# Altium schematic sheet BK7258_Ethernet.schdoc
size 335 x 105 mm
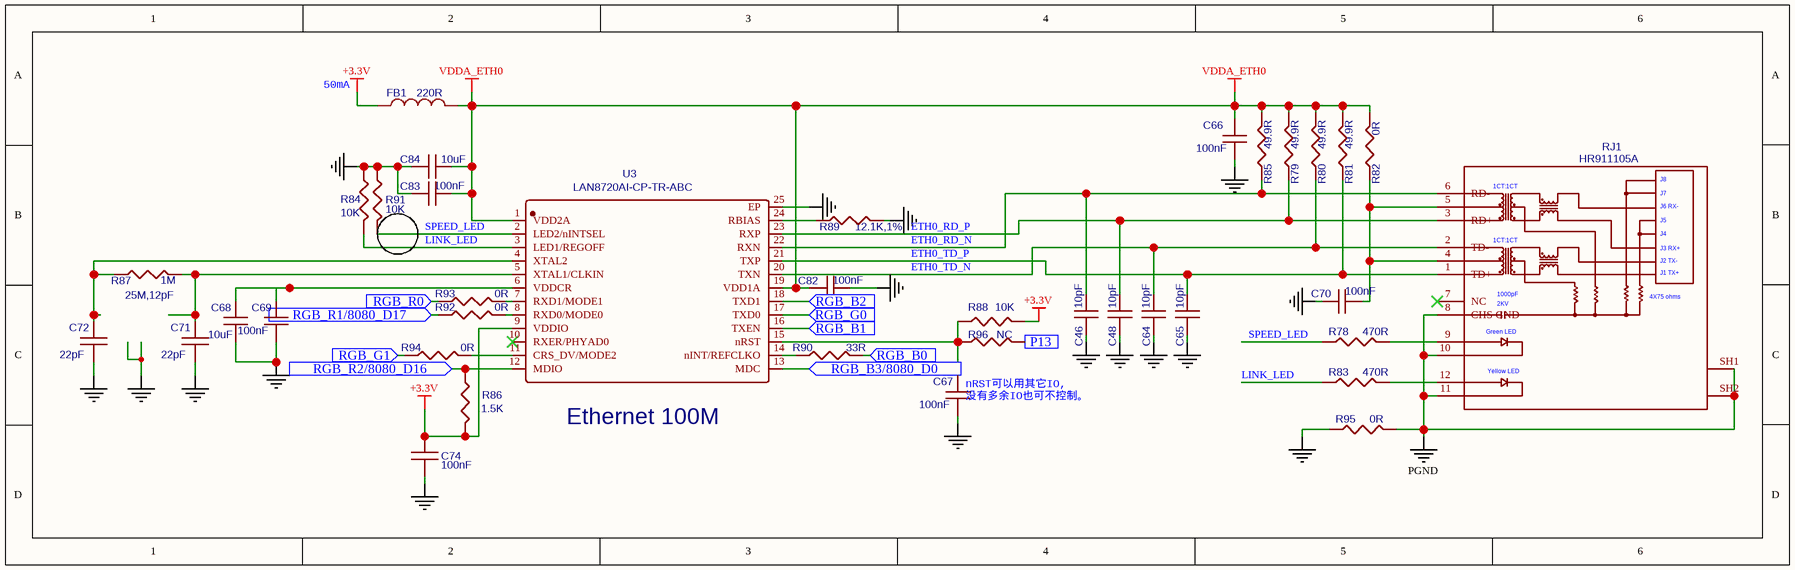
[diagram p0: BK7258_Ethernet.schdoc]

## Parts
C46  10pF  [C0402]
C48  10pF  [C0402]
C64  10pF  [C0402]
C65  10pF  [C0402]
C66  100nF  [C0402]
C67  100nF  [C0402]
C68  10uF  [C0402]
C69  100nF  [C0402]
C70  100nF  [C0402]
C71  22pF  [C0402]
C72  22pF  [C0402]
C74  100nF  [C0402]
C82  100nF  [C0402]
C83  100nF  [C0402]
C84  10uF  [C0402]
FB1  220R  [FB]
R78  470R  [R0402]
R79  49.9R  [R0402]
R80  49.9R  [R0402]
R81  49.9R  [R0402]
R82  0R  [R0402]
R83  470R  [R0402]
R84  10K  [R0402]
R85  49.9R  [R0402]
R86  1.5K  [R0402]
R87  1M  [R0402]
R88  10K  [R0402]
R89  12.1K,1%  [R0402]
R90  33R  [R0402]
R91  10K  [R0402]
R92  0R  [R0402]
R93  0R  [R0402]
R94  0R  [R0402]
R95  0R  [R0402]
R96  NC  [R0402]
RJ1  HR911105A  [RJ45-TH_HR911105A]
U3  LAN8720AI-CP-TR-ABC  [QFN-24_L4.0-W4.0-P0.50-TL-EP2.5]
X3  25M,12pF  [3225_2016]

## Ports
P13 (in), RGB_B0 (in), RGB_B1 (in), RGB_B2 (in), RGB_B3/8080_D0 (in), RGB_G0 (in), RGB_G1 (in), RGB_R0 (in), RGB_R1/8080_D17 (in), RGB_R2/8080_D16 (in)

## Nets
+3.3V: C74.1 FB1.P$1 R86.2 R88.2 U3.9(VDDIO)
GGND: C46.2 C48.2 C64.2 C65.2 C66.2 C67.2 C68.2 C69.2 C70.1 C71.2 C72.2 C74.2 C82.1 C83.2 C84.2 R84.1 R89.2 R91.1 R95.1 U3.25(EP)
PGND: R95.2 RJ1.8(CHS_GND) RJ1.10 RJ1.11 RJ1.SH1 RJ1.SH2
VDDA_ETH0: C66.1 C82.2 C83.1 C84.1 FB1.P$2 R79.2 R80.2 R81.2 R82.2 R85.2 U3.1(VDD2A) U3.19(VDD1A)
ETH0_RD_N: C46.1 R85.1 RJ1.6(RD-) U3.22(RXN)
ETH0_RD_P: C48.1 R79.1 RJ1.3(RD+) U3.23(RXP)
ETH0_TD_N: C64.1 R80.1 RJ1.2(TD-) U3.20(TXN)
ETH0_TD_P: C65.1 R81.1 RJ1.1(TD+) U3.21(TXP)
LINK_LED: R83.1 R84.2 U3.3(LED1/REGOFF)
P13: R96.2 ; port P13
RGB_B0: R90.2 ; port RGB_B0
RGB_B1: U3.16(TXEN) ; port RGB_B1
RGB_B2: U3.18(TXD1) ; port RGB_B2
RGB_B3/8080_D0: U3.13(MDC) ; port RGB_B3/8080_D0
RGB_G0: U3.17(TXD0) ; port RGB_G0
RGB_G1: R94.1 ; port RGB_G1
RGB_R0: R93.1 ; port RGB_R0
RGB_R1/8080_D17: R92.1 ; port RGB_R1/8080_D17
RGB_R2/8080_D16: R86.1 U3.12(MDIO) ; port RGB_R2/8080_D16
SPEED_LED: R78.1 R91.2 U3.2(LED2/nINTSEL)
NetC67_1: C67.1 R88.1 R96.1 U3.15(nRST)
NetC68_1: C68.1 C69.1 U3.6(VDDCR)
NetC70_2: C70.2 R82.1 RJ1.4 RJ1.5
NetC71_1: C71.1 R87.2 U3.5(XTAL1/CLKIN)
NetC72_1: C72.1 R87.1 U3.4(XTAL2)
NetR78_2: R78.2 RJ1.9
NetR83_2: R83.2 RJ1.12
NetR89_1: R89.1 U3.24(RBIAS)
NetR90_1: R90.1 U3.14(nINT/REFCLKO)
NetR92_2: R92.2 U3.8(RXD0/MODE0)
NetR93_2: R93.2 U3.7(RXD1/MODE1)
NetR94_2: R94.2 U3.11(CRS_DV/MODE2)

Not connected (* = marked no-connect by the designer): RJ1 7(NC)*; U3 10(RXER/PHYAD0)*

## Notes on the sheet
- (near FB1) 50mA
- (near C67) nRST可以用其它IO,
  没有多余IO也可不控制。
- (near U3) Ethernet 100M

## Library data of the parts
C46 C48 C64 C65 = 10pF: Manufacturer Part Number: 06035C103KAt2A; Manufacturer: AVX; APN: C006-0
C66 C67 C69 C70 C82 C83 = 100nF: Manufacturer Part Number: 06035C103KAt2A; Manufacturer: AVX; APN: C006-0
C68 C84 = 10uF: Manufacturer Part Number: 06035C103KAt2A; Manufacturer: AVX; APN: C006-0
C71 C72 = 22pF: Manufacturer: AVX; Manufacturer Part Number: 0805ZC105KAT2A; APN: C071-0
C74 = 100nF: Manufacturer: AVX; Manufacturer Part Number: 0805ZC105KAT2A; APN: C071-0
FB1 = 220R: Contributor: Adafruit
R78 R83 = 470R: Manufacturer Part Number: RM73B1JT240J; Manufacturer: KOA; APN: R125-0
R79-R81 R85 = 49.9R: Manufacturer Part Number: RM73B1JT240J; Manufacturer: KOA; APN: R125-0
R82 R92-R95 = 0R: Manufacturer Part Number: RM73B1JT240J; Manufacturer: KOA; APN: R125-0
R84 R88 R91 = 10K: Manufacturer Part Number: RM73B1JT240J; Manufacturer: KOA; APN: R125-0
R86 = 1.5K: Manufacturer Part Number: RM73B1JT240J; Manufacturer: KOA; APN: R125-0
R87 = 1M: Manufacturer Part Number: RM73B1JT240J; Manufacturer: KOA; APN: R125-0
R89 = 12.1K,1%: Manufacturer Part Number: RM73B1JT240J; Manufacturer: KOA; APN: R125-0
R90 = 33R: Manufacturer Part Number: RM73B1JT240J; Manufacturer: KOA; APN: R125-0
R96 = NC: Manufacturer Part Number: RM73B1JT240J; Manufacturer: KOA; APN: R125-0
RJ1 = HR911105A: BOM_Manufacturer: HANRUN; Contributor: LCSC
U3 = LAN8720AI-CP-TR-ABC: BOM_Manufacturer: MICROCHIP(美国微芯); Contributor: lcsc
X3 = 25M,12pF: BOM_Manufacturer: JWT; Manufacturer Part: CF4026M000739FA40000; Contributor: qunshan.xu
